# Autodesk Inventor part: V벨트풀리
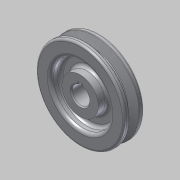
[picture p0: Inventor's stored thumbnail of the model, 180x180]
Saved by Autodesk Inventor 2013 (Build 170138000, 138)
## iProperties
Created: 2018-11
Part Number: V벨트풀리
Material: 알루미늄 6061
Document SubType Name: Modeling
Designer: mduedu
Density: 1 g/cm^3
Author: mduedu
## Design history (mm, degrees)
sketch "스케치1"
  geometry: L1 (-9.5, 0)-(9.5, 0); L2 (9.5, 0)-(9.5, 42.7); L3 (9.5, 42.7)-(-9.5, 42.7); L4 (-9.5, 42.7)-(-9.5, 0); L5 (-4.877, 42.7)-(-1.953, 33.7); L6 (-1.953, 33.7)-(1.953, 33.7); L7 (1.953, 33.7)-(4.877, 42.7); L8 (0, 0)-(0, 42.7); L9 (-9.5, 40)-(9.5, 40); 3 further points
  constraints: 18 end point, 8 point on line, 3 perpendicular, 2 midpoint, 2 parallel, 1 coincident, 1 horizontal, 1 other
  dimensions: "d0" = 85.4 diameter of L3 L1; "d2" = 19 distance of L2.end L3.end; "d3" = 80 diameter of L9 L1; "d4" = 36 deg angle of L7 L5; "d5" = 6.3 distance between parallel lines of L6 L9; "d6" = 8 distance of point (4, 40) point (-4, 40)
revolve "회전1" sketch "스케치1" stored, may be unused: angle "d7" = 90 deg
sketch "스케치2"
  geometry: L1 (-2.5, 8.124)-(2.5, 8.124); L2 (2.5, 8.124)-(2.5, 10.8); L3 (2.5, 10.8)-(-2.5, 10.8); L4 (-2.5, 10.8)-(-2.5, 8.124); A1 r 8.5 centre (0, 0) between (-2.5, 8.124) and (2.5, 8.124); 1 further point
  constraints: 8 end point, 2 parallel, 2 point on circle, 1 centre point, 1 coincident, 1 horizontal, 1 perpendicular
  dimensions: "d8" = 17 diameter of A1; "d10" = 19.3 dimension on A1 L3; "d11" = 5 distance of L2.end L3.end
extrude "돌출1" cut sketch "스케치2" stored distance "d12" = 10; taper "d13" = 0 deg
chamfer "모따기1" distance "d14" = 1; stored, may be unused: second distance "d15" = 2, angle "d16" = 45 deg
fillet "모깎기1" dims "d17" = 1, "d18" = 0.5, "d19" = 2
sketch "스케치3"
  geometry: C1 r 17.5 at (0, 0); C2 r 28.5 at (0, 0); 1 further point
  constraints: 2 centre point, 2 coincident
  dimensions: "d20" = 35 diameter of C1; "d23" = 57 diameter of C2
extrude "돌출2" cut sketch "스케치3" distance "d24" = 9.5; taper "d25" = 0 deg
fillet "모깎기2" dims "d26" = 3
node "솔리드1"
